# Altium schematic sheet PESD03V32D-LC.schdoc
size 127 x 101 mm
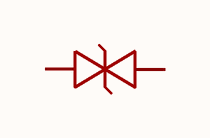
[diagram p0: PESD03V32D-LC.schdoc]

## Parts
D?  pesd03v32d-lc  [SOD-323_L1.7-W1.3-LS2.5-BI]  (value not drawn)

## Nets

Not connected (* = marked no-connect by the designer): D? 1 2

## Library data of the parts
D? = pesd03v32d-lc: 极性:双向;反向截止电压(Vrwm):3.3V;钳位电压:16V;峰值脉冲功率(Ppp):350W@8/20us;击穿电压:6V;; Manufacturer: TECH PUBLIC(台舟); AddInBom: yes; ModelId: 3c4d3117213c44d8be2b8463c3660d20; ModelTransform: 98.425,51.181,0,0,0,0,-0.001,0.006,0; Polarity: 双向; Reverse Stand-Off Voltage (Vrwm): 3.3V; Clamping Voltage: 16V; Voltage - Breakdown: 6V; Reverse Leakage Current (Ir): 200nA; Number of Channels: 单路; level of protection: IEC 61000-4-4；IEC 61000-4-2; Junction Capacitance: 1pF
